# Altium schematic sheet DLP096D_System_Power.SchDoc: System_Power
size 431 x 279 mm; Date: Not shown in title block; ApprovedBy: Not shown in title block; CheckedBy: Not shown in title block; Author: Not shown in title block; CompanyName: Not shown in title block; Engineer: Not shown in title block; Organization: Not shown in title block; Address1: Not shown in title block; Address2: Not shown in title block; Address3: Not shown in title block; Address4: Not shown in title block; DocumentNumber: 3; Revision: Use project parameter SCH_Rev; SheetNumber: 3; SheetTotal: 10; PageSetup: Record=PageOptions¦CenterHorizontal=True¦CenterVertical=True¦PrintScale=1.00¦XCorrection=1.00¦YCorrection=1.00¦PrintKind=0¦BorderSize=5000000¦LeftOffset=0¦BottomOffset=0¦Orientation=2¦PaperLength=1000¦PaperWidth=1000¦Scale=100¦PaperSource=15¦PrintQuality=600¦MediaType=1¦DitherType=10¦PaperKind=Letter¦PrintScaleMode=1
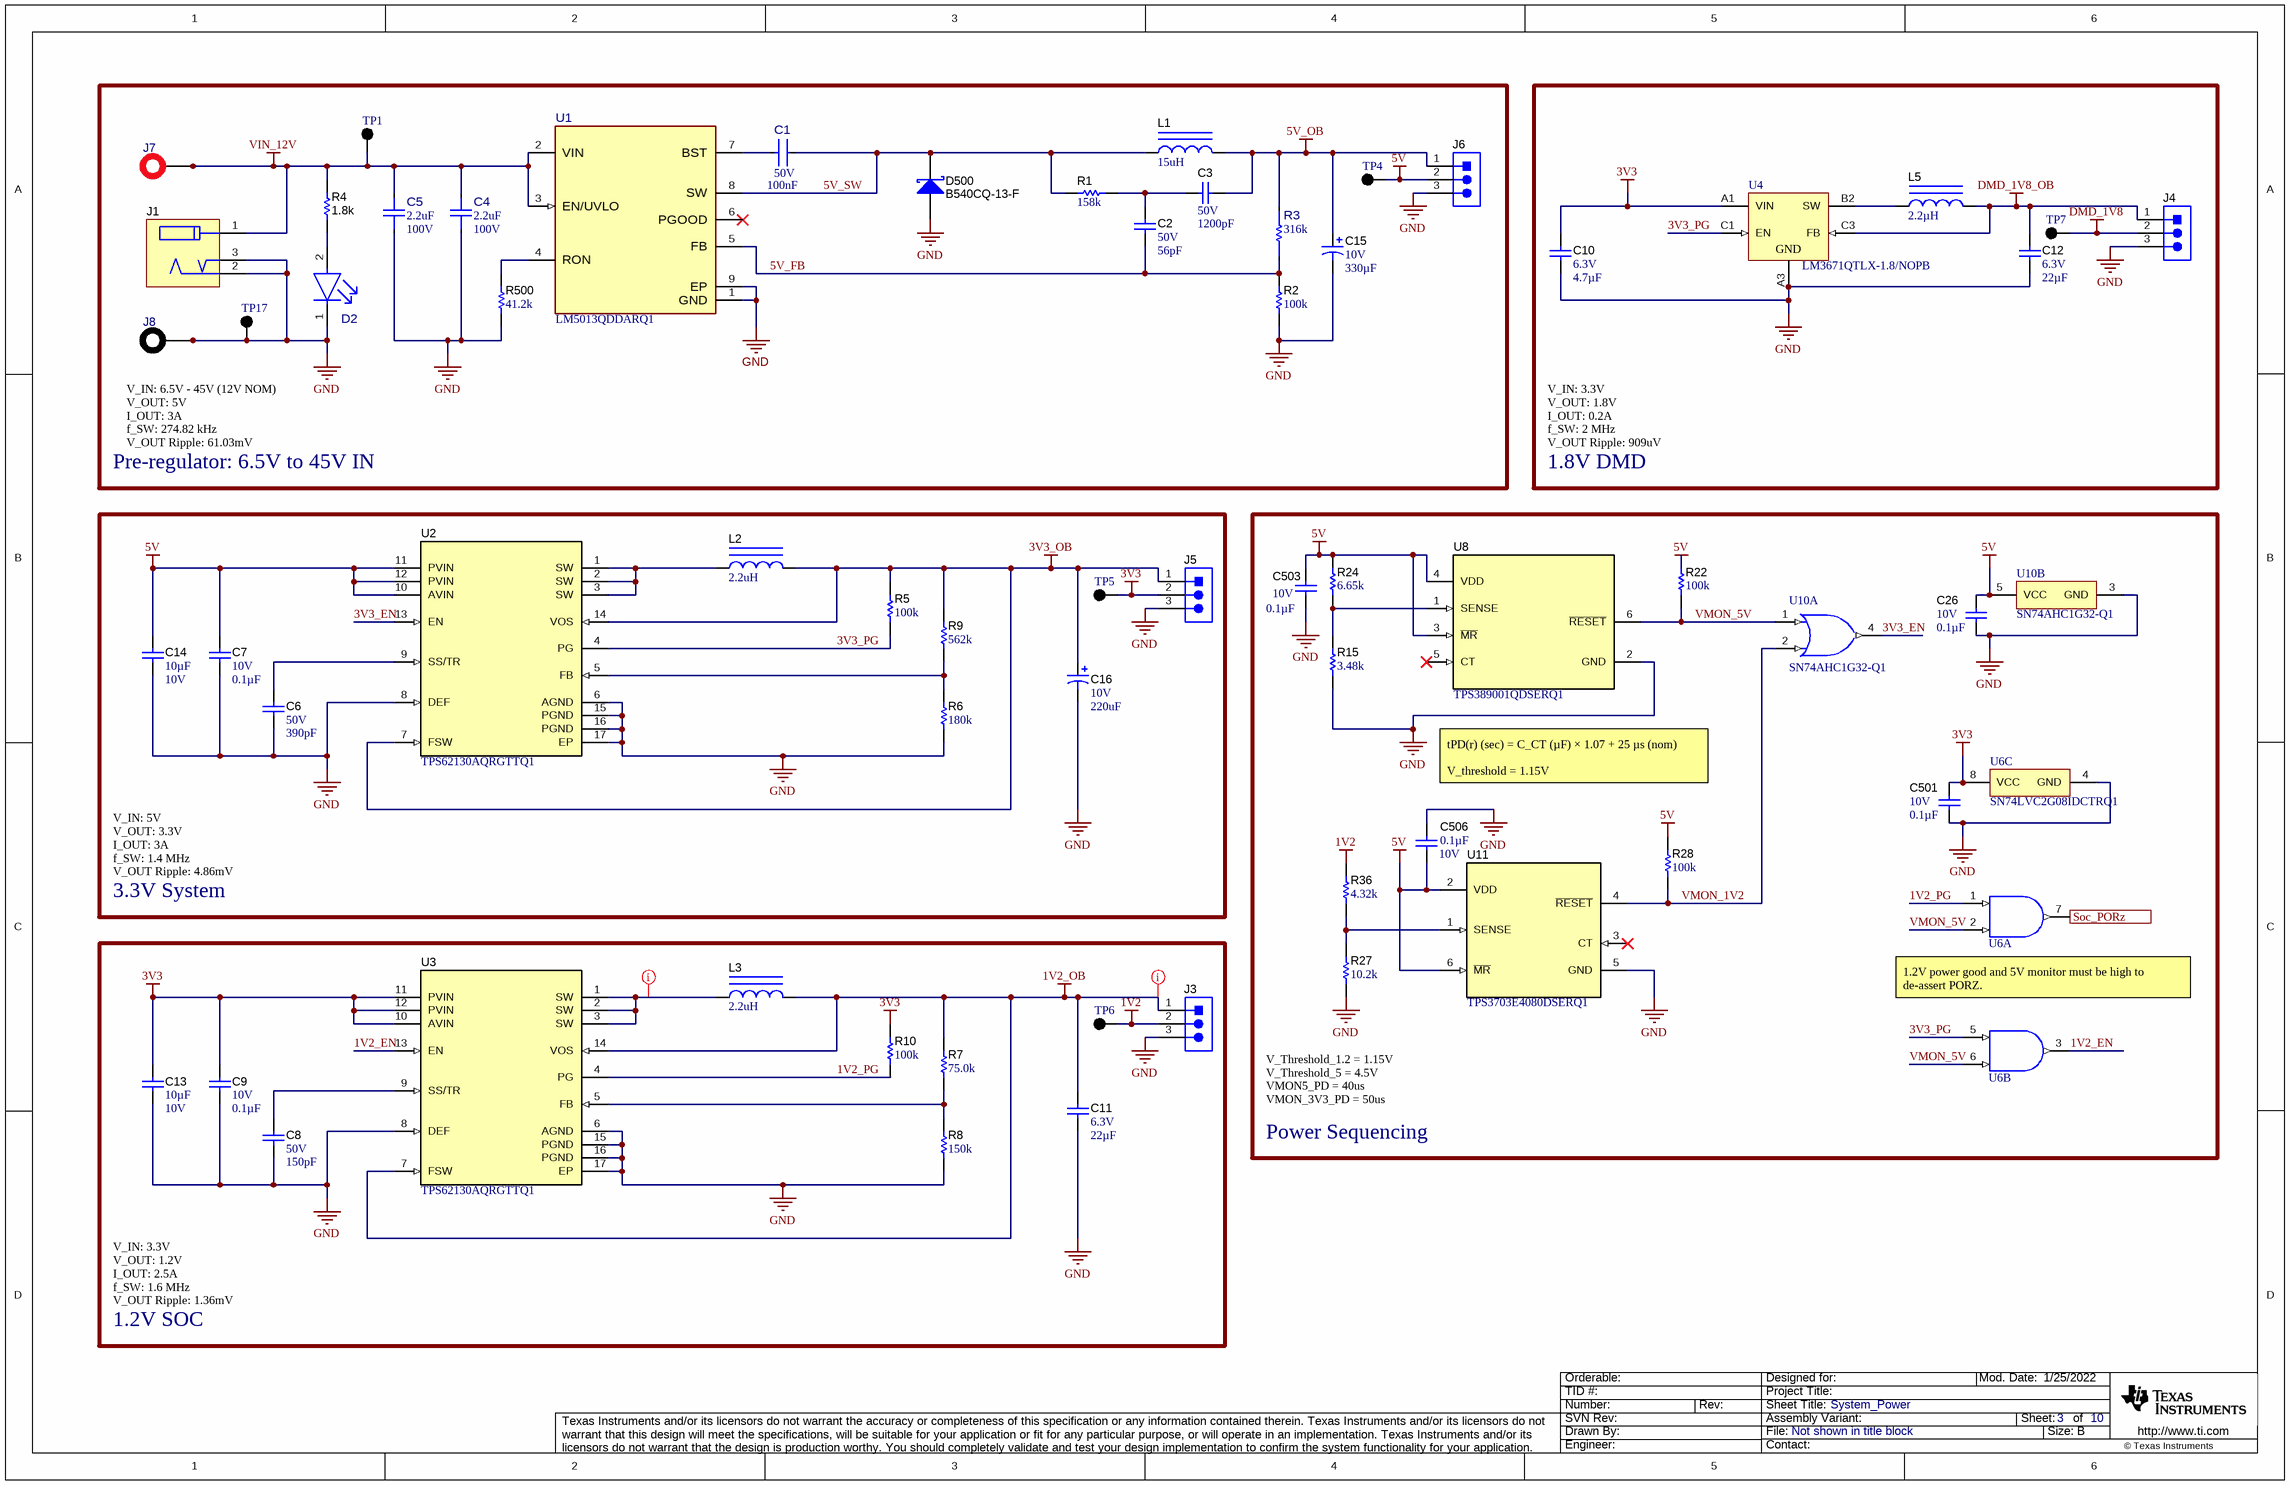
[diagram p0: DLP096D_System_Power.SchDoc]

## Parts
C1  Cap_F: 100nF  VDC_V: 50V  [FP-GCM188L81H104KA57D_0603-MFG]  (hidden comment: GCM188L81H104KA57D)
C2  VDC_V: 50V  ValueDisplayed: 56pF  [0603]  (hidden comment: 06035A560FAT2A)
C3  VDC_V: 50V  ValueDisplayed: 1200pF  [0603]  (hidden comment: GRM1885C1H122JA01D)
C4  ValueDisplayed: 2.2uF  VDC_V: 100V  [FP-GCJ32DL8EL225KA07L_1210-MFG]  (hidden comment: GCJ32DL8EL225KA07L)
C5  ValueDisplayed: 2.2uF  VDC_V: 100V  [FP-GCJ32DL8EL225KA07L_1210-MFG]  (hidden comment: GCJ32DL8EL225KA07L)
C6  VDC_V: 50V  ValueDisplayed: 390pF  [0402]  (hidden comment: GCM155R71H391KA37D)
C7  VDC_V: 10V  ValueDisplayed: 0.1µF  [0402]  (hidden comment: C0402C104K8RACTU)
C8  VDC_V: 50V  ValueDisplayed: 150pF  [0402]  (hidden comment: CGA2B2C0G1H151J050BA)
C9  VDC_V: 10V  ValueDisplayed: 0.1µF  [0402]  (hidden comment: C0402C104K8RACTU)
C10  VDC_V: 6.3V  ValueDisplayed: 4.7µF  [0402]  (hidden comment: GRM155R60J475ME47J)
C11  VDC_V: 6.3V  ValueDisplayed: 22µF  [0603]  (hidden comment: GRM186R60J226ME15D)
C12  VDC_V: 6.3V  ValueDisplayed: 22µF  [0603]  (hidden comment: GRM186R60J226ME15D)
C13  ValueDisplayed: 10µF  VDC_V: 10V  [0805_HV]  (hidden comment: CC0805ZKY5V6BB106)
C14  ValueDisplayed: 10µF  VDC_V: 10V  [0805_HV]  (hidden comment: CC0805ZKY5V6BB106)
C15  VDC_V: 10V  ValueDisplayed: 330µF  [CL_800x1000]  (hidden comment: UCL1A331MNL1GS)
C16  VDC_V: 10V  ValueDisplayed: 220uF  [SM_RADIAL_6.3BMM]  (hidden comment: UUD1A221MCL1GS)
C26  VDC_V: 10V  ValueDisplayed: 0.1µF  [0402]  (hidden comment: C0402C104K8RACTU)
C501  VDC_V: 10V  ValueDisplayed: 0.1µF  [0402]  (hidden comment: C0402C104K8RACTU)
C503  VDC_V: 10V  ValueDisplayed: 0.1µF  [0402]  (hidden comment: C0402C104K8RACTU)
C506  VDC_V: 10V  ValueDisplayed: 0.1µF  [0402]  (hidden comment: C0402C104K8RACTU)
D2  LSL29K-G1H2-1-Z  [FP-LSL29K-G1H2-1-Z_0603-0]  (value not drawn)
D500  B540CQ-13-F  [SMC]
J1  EJ508A  [Memory_EJ508A]  (value not drawn)
J3  22284033  [Molex_0022284033]  (value not drawn)
J4  22284033  [Molex_0022284033]  (value not drawn)
J5  22284033  [Molex_0022284033]  (value not drawn)
J6  22284033  [Molex_0022284033]  (value not drawn)
J7  571-0500  [571-0500]  (value not drawn)
J8  571-0100  [571-0100]  (value not drawn)
L1  ValueDisplayed: 15uH  [MSS1210]  (hidden comment: MSS1210-153ME)
L2  ValueDisplayed: 2.2uH  [XAL5030]  (hidden comment: XAL5030-222MEB)
L3  ValueDisplayed: 2.2uH  [XAL5030]  (hidden comment: XAL5030-222MEB)
L5  ValueDisplayed: 2.2µH  [0805_HV]  (hidden comment: MLP2012V2R2MT0S1)
R1  ValueDisplayed: 158k  [0603]  (hidden comment: CRCW0603158KFKEA)
R2  ValueDisplayed: 100k  [0603]  (hidden comment: CRCW0603100KFKEA)
R3  value 316k  [FP-CR0603-FX-3163ELF_0603-MFG]  (hidden comment: CR0603-FX-3163ELF)
R4  ValueDisplayed: 1.8k  [0402L]  (hidden comment: CRCW04021K80JNED)
R5  ValueDisplayed: 100k  [0805_HV]  (hidden comment: ERJ-6ENF1003V)
R6  ValueDisplayed: 180k  [0603]  (hidden comment: RC0603FR-07180KL)
R7  ValueDisplayed: 75.0k  [0603]  (hidden comment: RC0603FR-0775KL)
R8  ValueDisplayed: 150k  [0603]  (hidden comment: RC0603FR-07150KL)
R9  ValueDisplayed: 562k  [0603]  (hidden comment: RC0603FR-07562KL)
R10  ValueDisplayed: 100k  [0805_HV]  (hidden comment: ERJ-6ENF1003V)
R15  ValueDisplayed: 3.48k  [1206]  (hidden comment: ERJ-8ENF3481V)
R22  ValueDisplayed: 100k  [0805_HV]  (hidden comment: ERJ-6ENF1003V)
R24  ValueDisplayed: 6.65k  [0805_HV]  (hidden comment: ERJ-6ENF6651V)
R27  ValueDisplayed: 10.2k  [0805_HV]  (hidden comment: CRCW080510K2FKEA)
R28  ValueDisplayed: 100k  [0805_HV]  (hidden comment: ERJ-6ENF1003V)
R36  ValueDisplayed: 4.32k  [0603]  (hidden comment: RC0603FR-074K32L)
R500  ValueDisplayed: 41.2k  [0402]  (hidden comment: CRCW040241K2FKED)
TP1  5001  [Keystone5001]  (value not drawn)
TP4  5001  [Keystone5001]  (value not drawn)
TP5  5001  [Keystone5001]  (value not drawn)
TP6  5001  [Keystone5001]  (value not drawn)
TP7  5001  [Keystone5001]  (value not drawn)
TP17  5001  [Keystone5001]  (value not drawn)
U1  LM5013QDDARQ1  [DDA0008E-MFG]
U2  TPS62130AQRGTTQ1  [RGT0016C]
U3  TPS62130AQRGTTQ1  [RGT0016C]
U4  PartNumber: LM3671QTLX-1.8/NOPB  [YZR0005AEBA]  (hidden comment: LM3671TLX-1.8/NOPB)
U6  SN74LVC2G08IDCTRQ1  [DCT0008A_N]  (value not drawn)  (parts A,B,C of 3)
U8  TPS389001QDSERQ1  [DSE0006A]
U10  Generic Part Number: SN74AHC1G32-Q1  [DBV0005A_N]  (hidden comment: SN74AHC1G32TDBVRQ1)  (parts A,B of 2)
U11  TPS3703E4080DSERQ1  [DSE0006A]

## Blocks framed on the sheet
Pre-regulator: 6.5V to 45V IN: C1-C5 C15 D2 D500 J1 J6-J8 L1 R1-R4 R500 TP1 TP4 TP17 U1
1.8V DMD: C10 C12 J4 L5 TP7 U4
3.3V System: C6 C7 C14 C16 J5 L2 R5 R6 R9 TP5 U2
Power Sequencing: C26 C501 C503 C506 R15 R22 R24 R27 R28 R36 U6 U8 U10 U11
1.2V SOC: C8 C9 C11 C13 J3 L3 R7 R8 R10 TP6 U3

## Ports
Soc_PORz (out)

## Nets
1V2: J3.2 R36.2 TP6.1
1V2_OB: C11.1 J3.1 L3.2 R7.2 U3.7(FSW) U3.14(VOS)
3V3: C9.1 C10.1 C13.1 C501.1 J5.2 R10.2 TP5.1 U3.10(AVIN) U3.11(PVIN) U3.12(PVIN) U4.A1(VIN) U6.8(VCC)
3V3_OB: C16.1(+) J5.1 L2.2 R5.2 R9.2 U2.7(FSW) U2.14(VOS)
5V: C7.1 C14.1 C26.1 C503.1 C506.1 J6.2 R22.2 R24.2 R28.2 TP4.1 U2.10(AVIN) U2.11(PVIN) U2.12(PVIN) U8.3(~{MR}) U8.4(VDD) U10.5(VCC) U11.2(VDD) U11.6(~{MR})
5V_OB: C3.1 C15.1(+) J6.1 L1.2 R3.2
DMD_1V8: J4.2 TP7.1
DMD_1V8_OB: C12.1 J4.1 L5.2 U4.C3(FB)
GND: C4.1 C5.1 C6.2 C7.2 C8.2 C9.2 C10.2 C11.2 C12.2 C13.2 C14.2 C15.2(-) C16.2(-) C26.2 C501.2 C503.2 C506.2 D2.1(CATHODE) D500.2(A) J1.2 J1.3 J3.3 J4.3 J5.3 J6.3 J8.1 J8.2 R2.1 R6.1 R8.1 R15.1 R27.1 R500.1 TP17.1 U1.1(GND) U1.9(EP) U2.6(AGND) U2.8(DEF) U2.15(PGND) U2.16(PGND) U2.17(EP) U3.6(AGND) U3.8(DEF) U3.15(PGND) U3.16(PGND) U3.17(EP) U4.A3(GND) U6.4(GND) U8.2(GND) U10.3(GND) U11.5(GND)
VIN_12V: C4.2 C5.2 J1.1 J7.1 J7.2 R4.2 TP1.1 U1.2(VIN) U1.3(EN/UVLO)
1V2_EN: U3.13(EN) U6.3(2Y)
1V2_PG: R10.1 U3.4(PG) U6.1(1A)
3V3_EN: U2.13(EN) U10.4(Y)
3V3_PG: R5.1 U2.4(PG) U4.C1(EN) U6.5(2A)
5V_FB: C2.2 R2.2 R3.1 U1.5(FB)
5V_SW: C1.2 D500.1(K) L1.1 R1.1 U1.8(SW)
Soc_PORz: U6.7(1Y) ; port Soc_PORz
VMON_1V2: R28.1 U10.2(B) U11.4(~{RESET})
VMON_5V: R22.1 U6.2(1B) U6.6(2B) U8.6(~{RESET}) U10.1(A)
NetC1_1: C1.1 U1.7(BST)
NetC2_1: C2.1 C3.2 R1.2
NetC6_1: C6.1 U2.9(SS/TR)
NetC8_1: C8.1 U3.9(SS/TR)
NetD2_2: D2.2(ANODE) R4.1
NetL2_1: L2.1 U2.1(SW) U2.2(SW) U2.3(SW)
NetL3_1: L3.1 U3.1(SW) U3.2(SW) U3.3(SW)
NetL5_1: L5.1 U4.B2(SW)
NetR6_2: R6.2 R9.1 U2.5(FB)
NetR7_1: R7.1 R8.2 U3.5(FB)
NetR15_2: R15.2 R24.1 U8.1(SENSE)
NetR27_2: R27.2 R36.1 U11.1(SENSE)
NetR500_2: R500.2 U1.4(RON)

Not connected (* = marked no-connect by the designer): U1 6(PGOOD)*; U8 5(CT)*; U11 3(CT)*

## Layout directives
net class POWER; net class Voltage: 1V2_OB, NetL3_1

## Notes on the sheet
- V_IN: 6.5V - 45V (12V NOM)
  V_OUT: 5V
  I_OUT: 3A
  f_SW: 274.82 kHz
  V_OUT Ripple: 61.03mV
- V_IN: 3.3V
  V_OUT: 1.8V
  I_OUT: 0.2A
  f_SW: 2 MHz
  V_OUT Ripple: 909uV
- tPD(r) (sec) = C_CT (µF) × 1.07 + 25 µs (nom)
  V_threshold = 1.15V
- V_IN: 5V
  V_OUT: 3.3V
  I_OUT: 3A
  f_SW: 1.4 MHz
  V_OUT Ripple: 4.86mV
- (near U6) 1.2V power good and 5V monitor must be high to de-assert PORZ.
- V_Threshold_1.2 = 1.15V
  V_Threshold_5 = 4.5V
  VMON5_PD = 40us
  VMON_3V3_PD = 50us
- V_IN: 3.3V
  V_OUT: 1.2V
  I_OUT: 2.5A
  f_SW: 1.6 MHz
  V_OUT Ripple: 1.36mV

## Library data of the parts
C1 = CMP-0086535-1: 0.1µF ±10% 50V Ceramic Capacitor X8L 0603 (1608 Metric); Manufacturer: Murata Electronics North America; Symbol Name: SYM-GCM188L81H104KA57D; AEC Qualified: Yes; TempCo: -40+15%; SizeZ_mm: 0.9mm; AEC Grade: Grade 0
C2 = CMP-0006792-3: CAP, CERM, 56 pF, 50 V, +/- 1%, C0G/NP0, 0603; Manufacturer: AVX; TaMin_C: -55°C; Polarized: N; SizeAreaWB_mm2: 4.68; Value1: Unknown; U/M: EA; Value: 56pF; TaMax_C: 125°C; SizeZ_mm: 1; SizeX_mm: 1.6; SizeY_mm: 0.8; SizeArea_mm2: 1.28; AEC Category: Q200
C3 = CMP-0007180-1: CAP, CERM, 1200 pF, 50 V, +/- 5%, C0G/NP0, 0603; Manufacturer: MuRata; TaMin_C: -55°C; Polarized: N; SizeAreaWB_mm2: 4.68; Value1: Unknown; U/M: EA; Value: 1200pF; TaMax_C: 125°C; SizeZ_mm: 1; SizeX_mm: 1.6; SizeY_mm: 0.8; SizeArea_mm2: 1.28; Cap_F: 1.2nF; AEC Category: Q200
C4 C5 = CMP-0089367-1: 2.2µF ±10% 100V Ceramic Capacitor X8L 1210 (3225 Metric); Manufacturer: Murata; TempCo: +15/-40%; AEC Qualified: Yes; AEC Grade: Grade 0; SizeZ_mm: 2.3mm
C6 = CMP-0080703-2: CAP, CERM, 390 pF, 50 V,+/- 10%, X7R, AEC-Q200 Grade 1, 0402; Manufacturer: MuRata; SizeX_mm: 1; SizeZ_mm: 0.6; SizeY_mm: 0.5; AEC Qualified: Y; Value: 390pF; Polarized: N; AEC Category: Q200; TaMax_C: 125°C; TaMin_C: -55°C; SizeAreaWB_mm2: 3; U/M: EA
C7 C9 C26 C501 C503 C506 = CMP-0078241-1: CAP, CERM, 0.1 µF, 10 V,+/- 10%, X7R, 0402; Manufacturer: Kemet; TaMin_C: -55°C; Polarized: N; SizeAreaWB_mm2: 3; U/M: EA; Value: 0.1uF; TaMax_C: 125°C; SizeZ_mm: 0.6; SizeX_mm: 1; SizeY_mm: 0.5; Cap_F: 100nF; AEC Category: Q200
C8 = CMP-0006310-2: CAP, CERM, 150 pF, 50 V, +/- 5%, C0G/NP0, AEC-Q200 Grade 1, 0402; Manufacturer: TDK; TaMin_C: -55°C; Polarized: N; SizeAreaWB_mm2: 3; Value1: Unknown; U/M: EA; Value: 150pF; TaMax_C: 125°C; SizeZ_mm: 0.6; SizeX_mm: 1; SizeY_mm: 0.5; AEC Qualified: Y; AEC Category: Q200
C10 = CMP-0080385-1: CAP, CERM, 4.7 µF,  VAC/6.3 VDC,+/- 20%, X5R, 0402; Manufacturer: MuRata; TaMin_C: -55°C; ESR_ohm: 1m; Polarized: N; SizeAreaWB_mm2: 3; Value1: 0.001 ohm; U/M: EA; Value: 4.7uF; TaMax_C: 85°C; SizeZ_mm: 0.6; SizeX_mm: 1; SizeY_mm: 0.5; AEC Category: Q200
C11 C12 = CMP-0078295-1: CAP, CERM, 22 µF, 6.3 V,+/- 20%, X5R, 0603; Manufacturer: MuRata; TaMin_C: -55°C; Polarized: N; SizeAreaWB_mm2: 4.68; U/M: EA; Value: 22uF; TaMax_C: 85°C; SizeZ_mm: 1; SizeX_mm: 1.6; SizeY_mm: 0.8; SizeArea_mm2: 1.28; AEC Category: Q200
C13 C14 = CMP-0085574-1: CAP, CERM, 10 µF, 10 V,+80/-20%, Y5V, 0805; Manufacturer: Yageo; AEC Category: Q200; Cap_Case: 0805; SizeY_mm: 1.25; AEC Qualified: N; SizeX_mm: 2; Tolerance_%: 80%; TaMax_C: 85°C; TaMin_C: -30°C; Green_Lifecycle: Active; Green_REACh: Incomplete; Value: 10uF; U/M: EA; SizeAreaWB_mm2: 6.75; SizeZ_mm: 1.45; SizeArea_mm2: 2.5
C15 = CMP-0081924-1: CAP, AL, 330 µF, 10 V, +/- 20%, SMD; Manufacturer: Nichicon; IRMS_A: 850mA; SizeZ_mm: 10.5; AEC Qualified: N; Value: 330uF; TaMin_C: -55°C; Polarized: Y; SizeAreaWB_mm2: 112.27; U/M: EA; TaMax_C: 105°C; SizeX_mm: 8.9; SizeY_mm: 8.3; Cap_Case: 8x10mm; SizeArea_mm2: 73.87; CompType: Capacitor; AEC Category: Q200
C16 = CMP-0011112-1: CAP, AL, 220 uF, 10 V, +/- 20%, 0.34 ohm, SMD; Manufacturer: Nichicon; TaMin_C: -55°C; Polarized: Y; SizeAreaWB_mm2: 79.98; U/M: EA; Value: 220uF; TaMax_C: 105°C; SizeZ_mm: 7.7; SizeX_mm: 7.3; SizeY_mm: 6.6; Cap_Case: 6.3x7.7; SizeArea_mm2: 48.18; CompType: Capacitor; Cap_F: 220µF; AEC Category: Q200; ESR_ohm: 0.34; IRMS_A: 280mA
D2 = CMP-0092845-1: LED Uni-Color Red 643nm 2-Pin Chip 0603(1608Metric) T/R; Manufacturer: OSRAM Opto Semiconductors; AEC Grade: Grade 2; LuminousFlux_PhiV: 8.1/16.1lm; Vf_V: 1.8V; Forward Current: 2mA; Led Orientation: Top View; SizeZ_mm: 0.67mm; AEC Qualified: Yes; Luminous Intensity: 1.8-2.24/3.55-4.5mcd; Vr_V: 12V; Angle: 160°; LambdaD: 630nm; Tjmax_C: 110°C
D500 = CMP-0077948-2: Diode, Schottky, 40 V, 5 A, AEC-Q101, SMC; Manufacturer: Diodes Inc.; AEC Category: Q101; SizeAreaWB_mm2: 83.2686; SizeX_mm: 8.13; Vf_V: 550mV; TJmax_C: 150°C; RJC_CperW: 10; Vr_V: 40V; SizeZ_mm: 2.6; AEC Qualified: Y; Value1: 5A; Value: 40V; Value2: 0.55V; SizeArea_mm2: 50.5686; SizeY_mm: 6.22
J1 = CMP-0055800-1: Power Jack, 2.1x5.5mm, R/A, TH; Manufacturer: Memory Protection Devices; CNHeader: FALSE; Current_A: 5A; Gender: Male; Voltage_V: 12V
J3-J6 = CMP-0055332-1: Header, 2.54mm, 3x1, Tin, TH; Manufacturer: Molex; CNHeader: TRUE; Current_A: 4A; Shrouded: N; Gender: Male; Voltage_V: 250V; Row_Count: 1; Pitch_mm: 2.54; CT: FALSE; Cert_UL: Y
J7 = CMP-0055393-3: Standard Banana Jack, insulated, 10A, red; Manufacturer: DEM Manufacturing; Green_REACh: Incomplete; Green_Lifecycle: Not Set
J8 = CMP-0055389-3: Standard Banana Jack, insulated, 10A, black; Manufacturer: DEM Manufacturing; Green_REACh: Incomplete; Green_Lifecycle: Not Set
L1 = CMP-0061454-2: Inductor, Shielded, Ferrite, 15 uH, 8.7 A, 0.019 ohm, SMD; Manufacturer: Coilcraft; Isat: 10.7A @ 30% inductance drop; Irms: 8.7A @ 40C rise; Green_Lifecycle: Not Set; SizeAreaWB_mm2: 204.49; DCR_ohm: 19m; Green_REACh: Incomplete; Value: 15uH; Imax_A: 8.7A; SizeZ_mm: 10; SizeX_mm: 12.3; SizeArea_mm2: 151.29; Ind_H: 15µH; AEC Category: Q200
L2 L3 = CMP-0061001-2: Inductor, Shielded, Composite, 2.2 µH, 9.2 A, 0.01 ohm, AEC-Q200 Grade 1, SMD; Manufacturer: Coilcraft; Isat: 12.9A @ 30% inductance drop; Irms: 9.2A @ 40C rise; Green_Lifecycle: Not Set; SizeAreaWB_mm2: 54.4544; DCR_ohm: 10m; Green_REACh: Incomplete; Value: 2.2uH; Imax_A: 9.2A; SizeZ_mm: 3.1; SizeX_mm: 5.28; SizeY_mm: 5.48; SizeArea_mm2: 28.9344; Ind_H: 2.2µH; AEC Qualified: 1; AEC Category: Q200; AEC Grade: Y
L5 = CMP-0082247-1: Inductor, Shielded, Ferrite, 2.2 µH, 0.7 A, 0.364 ohm, SMD; Manufacturer: TDK; Irms: 0.7A @ 40C rise; SizeAreaWB_mm2: 6.75; DCR_ohm: 0.364; Value: 2.2uH; Imax_A: 700mA; SizeZ_mm: 1.45; SizeX_mm: 2; SizeY_mm: 1.25; Value2: 0.7A; SizeArea_mm2: 2.5; AEC Qualified: N; AEC Category: Q200
R1 = CMP-0022064-1: RES, 158 k, 1%, 0.1 W, 0603; Manufacturer: Vishay-Dale; Power_W: 100mW; TempCo: 100 ppm/C; U/M: EA; Value: 158k; EIA_Code: E96; SizeX_mm: 1.6; SizeY_mm: 0.8; SizeZ_mm: 1; Value2: 0.1W; SizeArea_mm2: 1.28; VDC_V: 75V; AEC Category: Q200
R2 = CMP-0021990-4: RES, 100 k, 1%, 0.1 W, AEC-Q200 Grade 0, 0603; Manufacturer: Vishay-Dale; Power_W: 100mW; TempCo: 100 ppm/C; Value: 100k; EIA_Code: E96; SizeX_mm: 1.6; SizeY_mm: 0.8; SizeZ_mm: 1; Value2: 0.1W; SizeArea_mm2: 1.28; AEC Qualified: Y; VDC_V: 75V; AEC Category: Q200; AEC Grade: 0
R3 = CMP-0093627-1: Thick Film Chip Resistors 0603 316kΩ 0.1W 1% 100ppm/°C; Manufacturer: Bourns; AEC Qualified: No; SizeZ_mm: 0.55mm; Power_W: 100mW; VDC_V: 75V
R4 = CMP-0026858-5: RES, 1.8 k, 5%, 0.063 W, AEC-Q200 Grade 0, 0402; Manufacturer: Vishay-Dale; Power_W: 63mW; TempCo: 200 ppm/C; Value_Code: 1k80; Value: 1.8k; EIA_Code: E24; SizeX_mm: 1; SizeY_mm: 0.5; SizeZ_mm: 0.6; Value2: 0.063W; AEC Qualified: Y; VDC_V: 50V; AEC Category: Q200; AEC Grade: 0
R5 R10 R22 R28 = CMP-0021521-3: RES, 100 k, 1%, 0.125 W, AEC-Q200 Grade 0, 0805; Manufacturer: Panasonic; Power_W: 125mW; TempCo: 100 ppm/C; Value: 100k; EIA_Code: E96; SizeX_mm: 2; SizeY_mm: 1.25; SizeZ_mm: 1.45; Value2: 0.125W; SizeArea_mm2: 2.5; AEC Qualified: Y; AEC Category: Q200; AEC Grade: 0; SizeAreaWB_mm2: 6.75
R6 = CMP-0022844-4: RES, 180 k, 1%, 0.1 W, 0603; Manufacturer: Yageo; Power_W: 100mW; TempCo: 100 ppm/C; Value: 180k; SizeX_mm: 1.6; SizeY_mm: 0.8; SizeZ_mm: 1; Value2: 0.1W; SizeArea_mm2: 1.28; AEC Qualified: N; VDC_V: 75V; AEC Category: Q200; SizeAreaWB_mm2: 4.68
R7 = CMP-0023267-5: RES, 75.0 k, 1%, 0.1 W, 0603; Manufacturer: Yageo; Power_W: 100mW; TempCo: 100 ppm/C; Value_Code: 75k0; Value: 75.0k; EIA_Code: E96; Res_ohm: 75k; SizeX_mm: 1.6; SizeY_mm: 0.8; SizeZ_mm: 1; Value2: 0.1W; SizeArea_mm2: 1.28; AEC Qualified: N; VDC_V: 75V; AEC Category: Q200; SizeAreaWB_mm2: 4.68
R8 = CMP-0022808-4: RES, 150 k, 1%, 0.1 W, 0603; Manufacturer: Yageo; Power_W: 100mW; TempCo: 100 ppm/C; Value: 150k; EIA_Code: E96; SizeX_mm: 1.6; SizeY_mm: 0.8; SizeZ_mm: 1; Value2: 0.1W; SizeArea_mm2: 1.28; AEC Qualified: N; VDC_V: 75V; AEC Category: Q200; SizeAreaWB_mm2: 4.68
R9 = CMP-0023184-4: RES, 562 k, 1%, 0.1 W, 0603; Manufacturer: Yageo; Power_W: 100mW; TempCo: 100 ppm/C; Value: 562k; EIA_Code: E96; SizeX_mm: 1.6; SizeY_mm: 0.8; SizeZ_mm: 1; Value2: 0.1W; SizeArea_mm2: 1.28; AEC Qualified: N; VDC_V: 75V; AEC Category: Q200; SizeAreaWB_mm2: 4.68
R15 = CMP-0017552-3: RES, 3.48 k, 1%, 0.25 W, AEC-Q200 Grade 0, 1206; Manufacturer: Panasonic; Power_W: 250mW; TempCo: 100 ppm/C; Value_Code: 3k48; Value: 3.48k; EIA_Code: E96; SizeX_mm: 3.2; SizeY_mm: 1.6; SizeZ_mm: 1.35; Value2: 0.25W; SizeArea_mm2: 5.12; AEC Qualified: Y; VDC_V: 200V; AEC Category: Q200; AEC Grade: 0; SizeAreaWB_mm2: 10.92
R24 = CMP-0021770-3: RES, 6.65 k, 1%, 0.125 W, AEC-Q200 Grade 0, 0805; Manufacturer: Panasonic; Power_W: 125mW; TempCo: 100 ppm/C; Value_Code: 6k65; Value: 6.65k; EIA_Code: E96; SizeX_mm: 2; SizeY_mm: 1.25; SizeZ_mm: 1.45; Value2: 0.125W; SizeArea_mm2: 2.5; AEC Qualified: Y; AEC Category: Q200; AEC Grade: 0; SizeAreaWB_mm2: 6.75
R27 = CMP-0020843-1: RES, 10.2 k, 1%, 0.125 W, 0805; Manufacturer: Vishay-Dale; Power_W: 125mW; TempCo: 100 ppm/C; Value_Code: 10k2; U/M: EA; Value: 10.2k; EIA_Code: E96; SizeX_mm: 2; SizeY_mm: 1.25; SizeZ_mm: 1.45; Value2: 0.125W; SizeArea_mm2: 2.5; VDC_V: 150V; AEC Category: Q200
R36 = CMP-0023147-2: RES, 4.32 k, 1%, 0.1 W, 0603; Manufacturer: Yageo America; Power_W: 100mW; TempCo: 200 ppm/C; Value_Code: 4k32; U/M: EA; Value: 4.32k; EIA_Code: E96; SizeX_mm: 1.6; SizeY_mm: 0.8; SizeZ_mm: 1; Value2: 0.1W; SizeArea_mm2: 1.28; VDC_V: 150V; AEC Category: Q200
R500 = CMP-0026371-2: RES, 41.2 k, 1%, 0.063 W, AEC-Q200 Grade 0, 0402; Manufacturer: Vishay-Dale; Power_W: 63mW; TempCo: 100 ppm/C; Value_Code: 41k2; Value: 41.2k; EIA_Code: E96; SizeX_mm: 1; SizeY_mm: 0.5; SizeZ_mm: 0.6; Value2: 0.063W; AEC Qualified: Y; VDC_V: 50V; AEC Category: Q200; AEC Grade: 0
TP1 TP4-TP7 TP17 = CMP-0055138-1: Test Point, Miniature, Black, TH; Manufacturer: Keystone; CNHeader: FALSE; Green_Lifecycle: Active; Green_REACh: Passed; ContactFinish: Silver; CT: TRUE
U1 = CMP-0091061-1: 100-V Input, 3.5-A Non-Synchronous Buck DC/DC Converter with Ultra-low IQ; Manufacturer: Texas Instruments; AEC Qualified: Yes; Max Supply Voltage: 100V; Output Voltage: 1.2-90V; TaMax_C: +125°C; Standoff Height: 0mm; SizeZ_mm: 1.7mm; Max Duty Cycle: 100%; Min Supply Voltage: 6V; Nominal Supply Current: 300uA; Switching Frequency: 1MHz; Output Type: AdjustableProgrammable; Number Of Outputs: 1; AEC Grade: Grade 1; TJmax_C: +150°C; TaMin_C: -40°C
U2 U3 = CMP-0083641-1: TPS62130A-Q1 3 to 17-V 3-A Automotive Step-Down Converter in 3 × 3 QFN Package, RGT0016C (VQFN-16); Alternate PartNumber: TPS62130AQRGTRQ1; Alternate Manufacturer: Texas Instruments; SizeAreaWB_mm2: 16; SizeZ_mm: 1; SizeX_mm: 3; SizeArea_mm2: 9; CompType: IC; AEC Qualified: Y; AEC Category: Q200
U4 = CMP-0071334-1: 2MHz, 600mA Step-Down DC-DC Converter, 5-pin Micro SMD, Pb-Free; Manufacturer: Texas Instruments; High-Reliability: Y; PackageTopMarking: XV*I B; CompType: MiscPower
U6 = CMP-0051803-1: Automotive Catalog Dual 2-Input Positive-AND Gate, DCT0008A, LARGE T&R; Manufacturer: Texas Instruments; Generic Part Number: SN74LVC2G08-Q1; F @ Nom Voltage(Max)(Mhz): 150; ICC @ Nom Voltage(Max)(mA): 0.01; Input Type: CMOS/TTL; Output Type: CMOS; Logic: True; VCC(Max)(V): 5.5; Technology Family: LVC; Schmitt Trigger: No; Bits(#): 2; tpd @ Nom Voltage(Max)(ns): 9,5.1,4.7,3.8; VCC(Min)(V): 1.65; Voltage(Nom)(V): 1.8,2.5,3.3,5; Output Drive (IOL/IOH)(Max)(mA): 32/-32
U8 = CMP-0081409-1: Automotive Low-Quiescent-Current 1% Accurate Supervisor With Programmable Delay, DSE0006A (WSON-6); Alternate Manufacturer: Texas Instruments; SizeAreaWB_mm2: 6.25; SizeZ_mm: 0.8; SizeX_mm: 1.5; SizeArea_mm2: 2.25; CompType: IC; AEC Qualified: Y; AEC Category: Q200
U10 = CMP-0051598-1: Automotive Catalog Single 2-Input Positive-OR Gate, DBV0005A, LARGE T&R; Manufacturer: Texas Instruments; Output Type: CMOS; Bits(#): 1; Gate Type: OR; 3-State Output: No; VCC(Max)(V): 5.5; Voltage(Nom)(V): 3.3,5; Logic: True; tpd @ Nom Voltage(Max)(ns): 11.4,7.5; F @ Nom Voltage(Max)(Mhz): 75; Output Drive (IOL/IOH)(Max)(mA): 50/-50; Sub-Family: OR Gate; ICC @ Nom Voltage(Max)(mA): 0.01; Technology Family: AHC; VCC(Min)(V): 2
U11 = CMP-0750051-1: Overvoltage and Undervoltage Reset IC With Time Delay and Manual Reset, DSE0006A (WSON-6); Alternate Manufacturer: Texas Instruments; AEC Category: Q200; SizeY_mm: 1.5; AEC Qualified: Y; SizeAreaWB_mm2: 6.25; SizeZ_mm: 0.8; SizeArea_mm2: 2.25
